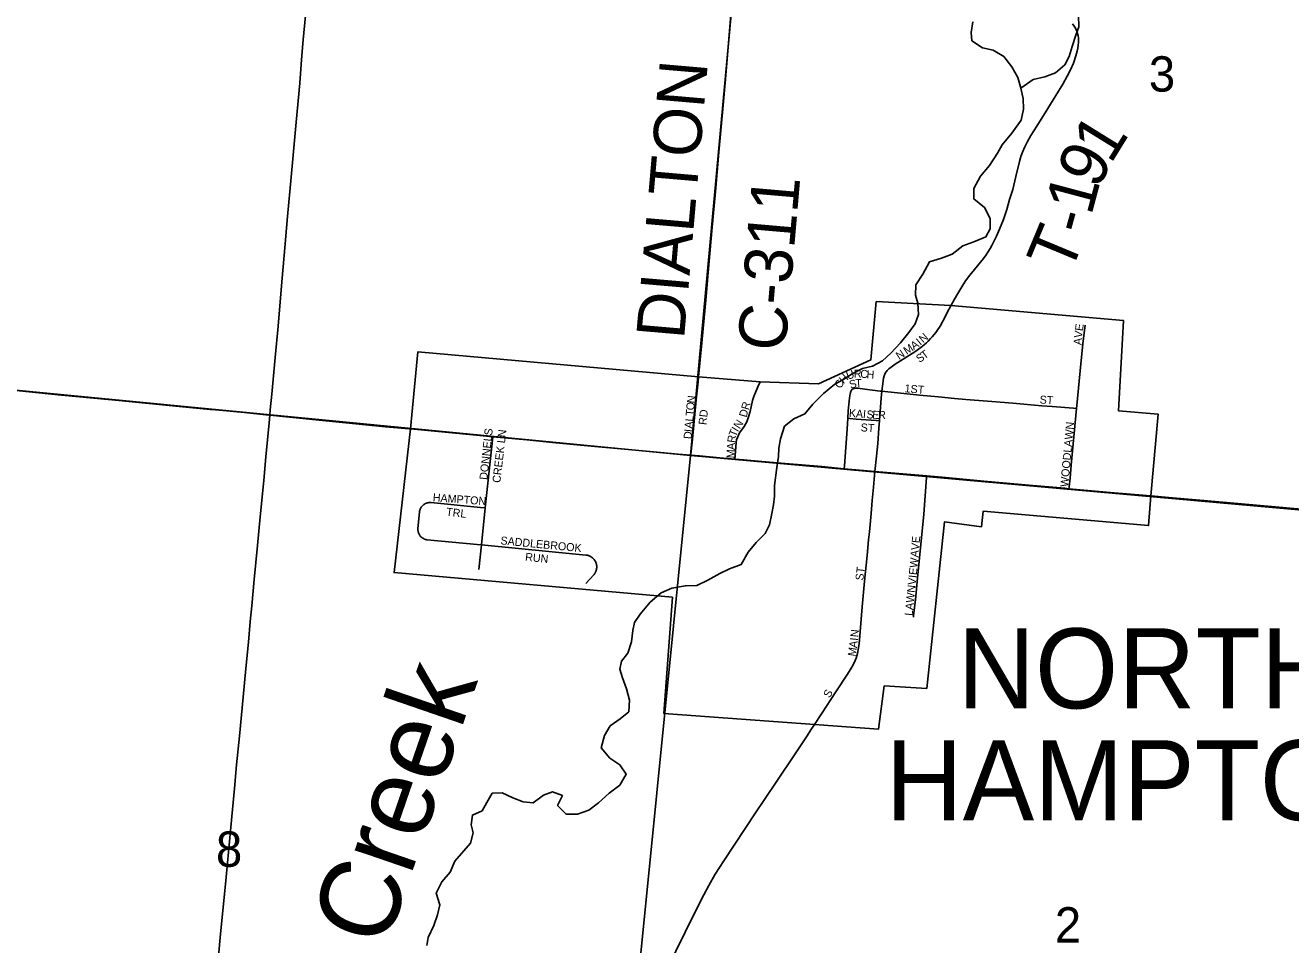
# Model space of a CAD drawing. Extents: x 1410790 to 1770854, y 566777 to 831614.
# Drawn here: x 1559702 to 1567610, y 725192 to 730938 of the extents above; entities that cross this region are included whole.
import ezdxf

# ---------------------------------------------------------------- set-up
doc = ezdxf.new("R2010")
doc.units = 0
for name, color, linetype in [('GM_X_City_Street', 7, 'Continuous'), ('GM_X_City_Street_Text', 7, 'Continuous'), ('GM_X_Corporation', 7, 'Continuous'), ('GM_X_Corporation_Text', 7, 'Continuous'), ('GM_X_County_Road', 7, 'Continuous'), ('GM_X_County_Road_Text', 7, 'Continuous'), ('GM_X_Minor_River', 7, 'Continuous'), ('GM_X_Minor_River_Text', 7, 'Continuous'), ('GM_X_Section', 7, 'Continuous'), ('GM_X_Section_Text', 7, 'Continuous'), ('GM_X_State_Route', 7, 'Continuous'), ('GM_X_Township_Road', 7, 'Continuous'), ('GM_X_Township_Road_Text', 7, 'Continuous')]:
    doc.layers.add(name, color=color, linetype=linetype)

msp = doc.modelspace()

# ---------------------------------------------------------------- linework, layer by layer
at = {"layer": 'GM_X_City_Street'}
for points in [[(1565055.7, 728650.6), (1565058.9, 728682.2), (1565060.2, 728698.3), (1565063.4, 728719.1), (1565065.8, 728733.3), (1565069.6, 728747.9), (1565072.8, 728756.9), (1565076.2, 728764.2), (1565081.1, 728772.2), (1565087.4, 728779.8), (1565098.4, 728790.9), (1565112.5, 728800.8), (1565139, 728820.8), (1565260.2, 728897.8), (1565299.5, 728924.6), (1565319.3, 728940.2), (1565333.5, 728953.4), (1565345.3, 728964.5), (1565359.9, 728980.1), (1565369.9, 728991), (1565382.1, 729005.5), (1565391.6, 729017.2), (1565401.2, 729030.5), (1565418.5, 729057.5), (1565449.9, 729115.6), (1565463.9, 729143.2), (1565485.7, 729185.7)], [(1566271.3, 728543.2), (1566273, 728560.9), (1566298, 728821.3), (1566313.3, 728966.5), (1566325.2, 729063.4)], [(1563860.9, 728251.6), (1563861.5, 728256.9), (1563872, 728350.6), (1563895.2, 728596.8), (1563907, 728709.7), (1563909.2, 728740.9)], [(1564136.6, 728226.6), (1564138.3, 728248.8), (1564144.8, 728330.5), (1564147.6, 728346.6), (1564152.1, 728362.3), (1564158.2, 728377.4), (1564166.4, 728391.6), (1564194.9, 728431.3), (1564203.2, 728445.4), (1564210.7, 728459.9), (1564222.2, 728491.8), (1564231.4, 728524), (1564247.3, 728593), (1564255.1, 728618.1), (1564279.8, 728678.5), (1564295, 728709.3)], [(1564841.5, 728482.3), (1564843.6, 728526.4), (1564849.8, 728591.8), (1564854.8, 728623.8), (1564856.3, 728633.4), (1564858.9, 728643.9), (1564861, 728649.6), (1564865.4, 728658.7)], [(1564865.4, 728658.7), (1564869.6, 728663.1), (1564875.1, 728666), (1564884.2, 728668.6), (1564892.3, 728669.4), (1564900.1, 728669.9), (1564910, 728669.4), (1564920.4, 728668.3), (1564948.4, 728664.5), (1565044.6, 728652.2), (1565055.7, 728650.6)], [(1565039.8, 728466.8), (1565040.1, 728471.1), (1565046, 728551.5), (1565051.2, 728608.1), (1565055.7, 728650.6)], [(1565055.7, 728650.6), (1565073.4, 728648.5), (1565290, 728625.8), (1565408.4, 728615.2), (1565508.2, 728606.3), (1565579.7, 728600.1), (1565741.9, 728586.9), (1565873.4, 728575.6), (1566054.3, 728560.1), (1566120.1, 728554.9), (1566253.6, 728544.6), (1566271.3, 728543.2)], [(1566224.3, 728041.7), (1566225.4, 728052.9), (1566231.3, 728108.5), (1566238.2, 728188.2), (1566254.6, 728366.5), (1566271.3, 728543.2)], [(1564819.6, 728166.6), (1564820.7, 728183.9), (1564830.6, 728299.5), (1564838.2, 728413.2), (1564841.5, 728482.3)], [(1564841.5, 728482.3), (1564855.2, 728481.1), (1564894.9, 728477.5), (1564957.3, 728473.1), (1565018.9, 728468.4), (1565039.8, 728466.8)], [(1565011.6, 728148.9), (1565021.4, 728245.1), (1565029, 728325.3), (1565036.3, 728420.4), (1565039.8, 728466.8)], [(1562576.7, 727922.5), (1562623, 728366.1), (1562623.1, 728366.7)], [(1564633.3, 726569.2), (1564677, 726635.4), (1564767.9, 726772.6), (1564840.3, 726882.3), (1564874.6, 726937.6), (1564888.8, 726967.4), (1564893.9, 726981.9), (1564902, 727012.3), (1564912.3, 727073), (1564932.3, 727303.4), (1564946.2, 727463.6), (1564962.7, 727623.9), (1564972.1, 727722.9), (1564977.3, 727772.5), (1564987.7, 727887.4), (1564995, 727968.3), (1565003, 728051.3), (1565007.5, 728101.3), (1565011.6, 728148.9)], [(1565252.9, 727238.9), (1565253.8, 727249.5), (1565264.9, 727347), (1565275.1, 727462.1), (1565290.8, 727610.6), (1565316.5, 727882.2), (1565334.4, 728112), (1565335.2, 728121.5)], [(1562576.7, 727922.5), (1562546.6, 727925.4), (1562235.8, 727955), (1562232.6, 727955.1), (1562229.4, 727955.2), (1562226.2, 727955), (1562223.1, 727954.7), (1562219.9, 727954.3), (1562216.8, 727953.7), (1562213.7, 727952.9), (1562210.7, 727952.1), (1562207.7, 727951), (1562204.7, 727949.8), (1562201.9, 727948.5), (1562199, 727947), (1562196.3, 727945.4), (1562193.6, 727943.7), (1562191.1, 727941.8), (1562188.6, 727939.8), (1562186.2, 727937.8), (1562183.9, 727935.5), (1562181.8, 727933.2), (1562179.7, 727930.8), (1562177.8, 727928.2), (1562176, 727925.6), (1562174.3, 727922.9), (1562172.8, 727920.2), (1562171.4, 727917.3), (1562170.1, 727914.4), (1562169, 727911.4), (1562168, 727908.4), (1562167.2, 727905.3), (1562166.6, 727902.3), (1562166, 727899.1), (1562165.7, 727896), (1562156.2, 727794), (1562155.9, 727790.9), (1562155.8, 727787.7), (1562155.9, 727784.5), (1562156.1, 727781.3), (1562156.5, 727778.1), (1562157, 727775), (1562157.6, 727771.9), (1562158.5, 727768.8), (1562159.5, 727765.8), (1562160.6, 727762.8), (1562161.9, 727759.9), (1562163.3, 727757), (1562164.9, 727754.3), (1562166.5, 727751.5), (1562168.4, 727748.9), (1562170.3, 727746.4), (1562172.4, 727744), (1562174.6, 727741.7), (1562176.9, 727739.5), (1562179.3, 727737.4), (1562181.8, 727735.4), (1562184.4, 727733.6), (1562187.1, 727731.8), (1562189.9, 727730.3), (1562192.7, 727728.8), (1562195.6, 727727.5), (1562198.6, 727726.4), (1562201.6, 727725.3), (1562204.7, 727724.5), (1562207.8, 727723.8), (1562210.9, 727723.2), (1562214.1, 727722.9), (1562525.2, 727693.4), (1562552.6, 727690.8)], [(1562552.6, 727690.8), (1562576.7, 727922.5)], [(1562536.5, 727536.5), (1562552.6, 727690.8)], [(1562552.6, 727690.8), (1563205.2, 727627.1), (1563208.6, 727626.7), (1563212, 727626.2), (1563215.3, 727625.5), (1563218.7, 727624.7), (1563222, 727623.7), (1563225.2, 727622.6), (1563228.4, 727621.3), (1563231.5, 727619.9), (1563234.6, 727618.3), (1563237.6, 727616.6), (1563240.4, 727614.8), (1563243.2, 727612.8), (1563246, 727610.7), (1563248.6, 727608.5), (1563251.1, 727606.1), (1563253.5, 727603.6), (1563255.7, 727601.1), (1563257.9, 727598.4), (1563259.9, 727595.7), (1563261.8, 727592.8), (1563263.6, 727589.9), (1563265.2, 727586.8), (1563266.7, 727583.7), (1563268.1, 727580.6), (1563269.2, 727577.4), (1563270.3, 727574.1), (1563271.2, 727570.8), (1563271.9, 727567.4), (1563272.5, 727564.1), (1563273, 727560.7), (1563273.2, 727557.2), (1563273.3, 727553.8), (1563273.3, 727550.3), (1563273.1, 727546.9), (1563272.7, 727543.5), (1563272.2, 727540.1), (1563271.5, 727536.8), (1563270.7, 727533.5), (1563269.7, 727530.1), (1563268.6, 727526.9), (1563267.3, 727523.7), (1563265.9, 727520.6), (1563264.3, 727517.5), (1563262.6, 727514.6), (1563260.8, 727511.7), (1563258.8, 727508.9), (1563256.7, 727506.2), (1563254.5, 727503.6), (1563205.5, 727448.5)]]:
    msp.add_lwpolyline(points, dxfattribs=at)
at = {"layer": 'GM_X_Corporation'}
msp.add_lwpolyline([(1563693.3, 726638), (1563746.3, 727363.8), (1562007.2, 727517.7), (1562109.2, 728415.5), (1562154.8, 728896.4), (1563909.2, 728740.9), (1564295, 728709.3), (1564659.7, 728696.6), (1564986.1, 728846.8), (1565020.1, 729211.8), (1565485.7, 729185.8), (1566564.4, 729093.2), (1566533.8, 728529.1), (1566781, 728508.1), (1566735.2, 727997.1), (1566722.1, 727811.8), (1565689, 727902.5), (1565677.2, 727804.6), (1565445.9, 727834.2), (1565335.7, 726793.5), (1565070.1, 726809.1), (1565034.7, 726540.1)], close=True, dxfattribs=at)
at = {"layer": 'GM_X_County_Road'}
for points in [[(1563909.2, 728740.9), (1563929.7, 728952.6), (1563956.3, 729242.8), (1563970, 729393.1), (1563993.5, 729654.4), (1564015.7, 729899.3), (1564036.7, 730144.3), (1564063.1, 730438.4), (1564078.1, 730601.6), (1564104.5, 730928.4), (1564122.4, 731140.8), (1564140, 731353.3), (1564176, 731761.6), (1564194.1, 731974.1), (1564208.8, 732137.3), (1564228.6, 732349.6), (1564247.7, 732561.9), (1564259.3, 732686)], [(1564587.6, 726498.1), (1564612.2, 726535.6), (1564633.3, 726569.2)], [(1563376.8, 724146.6), (1563381.6, 724160.4), (1563481.2, 724438.2), (1563571.2, 724684.6), (1563629.1, 724838), (1563672.2, 724944.2), (1563711.5, 725034.2), (1563768, 725152.5), (1563826.4, 725269.9), (1563927.4, 725476), (1563973.3, 725562.9), (1564014.1, 725633.8), (1564066.5, 725716.9), (1564266.2, 726017.2), (1564394, 726207.9), (1564513.1, 726384.8), (1564587.6, 726498.1)]]:
    msp.add_lwpolyline(points, dxfattribs=at)
at = {"layer": 'GM_X_Minor_River'}
for points in [[(1565922.9, 730545.4), (1566000, 730599.6), (1566074.4, 730616.7), (1566140.9, 730639.9), (1566197.7, 730691.3), (1566226.4, 730743.1), (1566245.2, 730805), (1566268.2, 730876.9), (1566286.8, 730928.8), (1566283.7, 730999), (1566274.6, 731075.3), (1566277.6, 731153.4), (1566294.4, 731219.4), (1566297.3, 731293.5), (1566276.2, 731365.9), (1566260.8, 731426.2), (1566287.8, 731494.1), (1566300.6, 731564.1), (1566291, 731657.4)], [(1565732.7, 729730.9), (1565697.4, 729799.5), (1565629.9, 729852.5), (1565630.7, 729918.7), (1565671.7, 729994.3), (1565728.7, 730061.8), (1565777.8, 730139.3), (1565806.5, 730191.1), (1565867.6, 730264.5), (1565924.7, 730346), (1565939.6, 730413.9), (1565938.4, 730480.1), (1565921.2, 730552.5), (1565903.9, 730610.8), (1565866.6, 730677.4), (1565817.3, 730742.2), (1565751.6, 730783.1), (1565683.6, 730798), (1565617.9, 730840.9), (1565612.6, 730893.1), (1565623.4, 730959.2)], [(1562211.5, 725187.7), (1562220.1, 725237.7), (1562255.1, 725311.5), (1562278, 725379.3), (1562292.8, 725441.3), (1562269.6, 725513.8), (1562304.6, 725585.5), (1562357.5, 725645), (1562386.4, 725714.8), (1562484, 725825.9), (1562500.9, 725891.9), (1562489.5, 725942.1), (1562496.2, 726002.2), (1562556.7, 726029.5), (1562587.4, 726081.3), (1562620.2, 726139), (1562682.4, 726140.2), (1562748.2, 726109.4), (1562814.1, 726084.5), (1562876.2, 726077.7), (1562941, 726127.1), (1562997.4, 726148.4), (1563059.3, 726123.6), (1563028.4, 726061.8), (1563081.9, 726007.1), (1563152.1, 726008.2), (1563224.6, 726033.4), (1563283.3, 726078.8), (1563350.3, 726140.1), (1563417, 726189.4), (1563458, 726257), (1563416.6, 726315.7), (1563354.9, 726358.5), (1563301.6, 726421.4), (1563322.6, 726499.3), (1563357.4, 726559), (1563420.1, 726604.3), (1563474.8, 726647.8), (1563477.7, 726719.9), (1563458.5, 726790.3), (1563433.3, 726860.8), (1563417.9, 726913.1), (1563428.5, 726963.1), (1563467.3, 727014.7), (1563490.2, 727084.6), (1563499.1, 727154.7), (1563509.7, 727204.7), (1563544.5, 727258.4), (1563607.6, 727331.8), (1563676.5, 727391), (1563743, 727420.3), (1563827.4, 727435.3), (1563899.6, 727436.4), (1563968.2, 727469.6), (1564043, 727512.8), (1564103.5, 727540.1), (1564176, 727567.3), (1564219, 727644.9), (1564269.9, 727706.5), (1564324.8, 727761.9), (1564353.5, 727815.7), (1564368.4, 727887.7), (1564377.1, 727941.7), (1564383.8, 727995.7), (1564384.6, 728061.9), (1564398, 728174), (1564408.9, 728244), (1564411.5, 728296.1), (1564422.3, 728354.1), (1564447.3, 728432), (1564506, 728479.3), (1564574.6, 728510.6), (1564623.5, 728570.1), (1564690.5, 728637.4), (1564761.4, 728694.7), (1564811.8, 728722.1), (1564870.5, 728759.5), (1564935, 728792.7), (1564997.4, 728808), (1565060, 728841.3), (1565110.7, 728888.8), (1565171.7, 728954.2), (1565224.6, 729017.6), (1565263.3, 729071.3), (1565284.1, 729131.2), (1565279, 729201.4), (1565265.6, 729251.7), (1565268.3, 729315.8), (1565311.3, 729383.4), (1565352.3, 729459.1), (1565426.8, 729482.2), (1565495.3, 729507.4), (1565560.1, 729560.7), (1565630.6, 729583.9), (1565705.2, 729615), (1565731.9, 729666.8), (1565732.7, 729730.9)]]:
    msp.add_lwpolyline(points, dxfattribs=at)
at = {"layer": 'GM_X_Section'}
for points in [[(1559098.4, 734120.8), (1564357.6, 733651.2), (1563860.1, 728250.4), (1558607.5, 728757.4)], [(1569584.1, 733136.2), (1569081.4, 727783.8), (1563860.1, 728250.4), (1564357.6, 733651.2)], [(1558607.5, 728757.4), (1563860.1, 728250.4), (1563332.6, 722968), (1558107.7, 723456.7)], [(1563860.1, 728250.4), (1569081.4, 727783.8), (1568614.4, 722540.4), (1563332.6, 722968)]]:
    msp.add_lwpolyline(points, close=True, dxfattribs=at)
at = {"layer": 'GM_X_State_Route'}
for points in [[(1560856.7, 728537.9), (1560663, 728556.3), (1560287.5, 728592.7), (1559928.4, 728627.3), (1559585.7, 728661.8)], [(1561224.7, 728502.4), (1561071.1, 728517.4), (1560891.5, 728534.6), (1560856.7, 728537.9)], [(1562104.5, 728416), (1562102, 728416.2), (1561952.2, 728429.1), (1561642.2, 728460.5), (1561332.2, 728491.9), (1561229.9, 728501.9), (1561224.7, 728502.4)], [(1566734.2, 727997.2), (1566685.9, 728001.6), (1566506.7, 728016.2), (1566224.3, 728041.7), (1566197.7, 728044.3), (1565998, 728062.7), (1565692.8, 728089.1), (1565431.4, 728113.4), (1565335.2, 728121.5), (1565011.6, 728148.9), (1564939.4, 728155.4), (1564819.6, 728166.6), (1564679.6, 728179.7), (1564451.5, 728199.9), (1564306, 728212), (1564190.7, 728221.8), (1564136.6, 728226.6), (1564042.5, 728235), (1563915.4, 728246.8), (1563860.9, 728251.6), (1563783.1, 728258.6), (1563651.9, 728270.4), (1563423.7, 728290.9), (1563261.6, 728305.8), (1563017.5, 728328.4), (1562836.9, 728347.5), (1562695.6, 728360.3), (1562623.1, 728366.7), (1562542.8, 728373.8), (1562109.2, 728415.5), (1562104.5, 728416)], [(1567770.5, 727905.1), (1567231.4, 727952.8), (1567019.1, 727971.7), (1566872, 727984.4), (1566735.2, 727997.1), (1566734.2, 727997.2)]]:
    msp.add_lwpolyline(points, dxfattribs=at)
at = {"layer": 'GM_X_Township_Road'}
for points in [[(1561229.9, 728501.9), (1561232.7, 728534.9), (1561242.1, 728632.7), (1561264.5, 728861.2), (1561282.4, 729057.2), (1561306.2, 729335), (1561319.4, 729498.5), (1561341.8, 729743.5), (1561363.6, 729988.6), (1561394.6, 730331.6), (1561417.2, 730576.6), (1561427.8, 730723.7), (1561439.3, 730846.4), (1561453.5, 730999.3)], [(1565485.7, 729185.7), (1565508.3, 729226.6), (1565529, 729262.1), (1565566.7, 729323.9), (1565577.7, 729340.9), (1565604.4, 729377.3), (1565633.1, 729411.8), (1565689.4, 729479.7), (1565706.6, 729503.5), (1565717.8, 729519.7), (1565732.5, 729543.4), (1565741.8, 729561.1), (1565770.7, 729619.5), (1565790.6, 729664.1), (1565814.7, 729724.5), (1565835.4, 729786.3), (1565853.7, 729849), (1565872.6, 729911.2), (1565892.1, 729993.2), (1565914.9, 730086.3), (1565924.1, 730117.6), (1565934.5, 730145.6), (1565948.3, 730179.3), (1565963.1, 730208.1), (1565986.9, 730249.5), (1566023, 730307.7), (1566091.4, 730417), (1566141.4, 730498.7), (1566185.1, 730570), (1566214, 730620.7), (1566233.6, 730658.8), (1566252.5, 730701.9), (1566268.2, 730746.9), (1566275.9, 730776.6), (1566279.5, 730795.1), (1566281.5, 730812.8), (1566283.1, 730830.5), (1566283.9, 730845.8), (1566283.1, 730860.3), (1566281.9, 730872.3), (1566278.7, 730886.8), (1566274.7, 730898.4), (1566269.8, 730908.9), (1566264.2, 730919.8), (1566256.2, 730933), (1566246.1, 730947.9)], [(1560900.9, 725025.7), (1560920.3, 725238), (1560956.9, 725613.3), (1560979.5, 725860), (1560997.4, 726037.8), (1561009.9, 726168.3), (1561022.2, 726315.4), (1561040.1, 726494.7), (1561063.9, 726739.5), (1561080.3, 726919.1), (1561097.2, 727082.1), (1561108.3, 727212.8), (1561118.1, 727310.7), (1561132.9, 727473.8), (1561153.4, 727686), (1561170.2, 727865.7), (1561192.6, 728094.2), (1561206, 728241.2), (1561225.9, 728453.3), (1561229.9, 728501.9)]]:
    msp.add_lwpolyline(points, dxfattribs=at)

# ---------------------------------------------------------------- texts
at = {"layer": 'GM_X_City_Street_Text'}
for s, rotation, p in [('N', 40.98626, (1565313.2, 728949.9)), ('V', 82.79095, (1566305.3, 728981.4)), ('E', 82.24467, (1566310.8, 729024.9)), ('M', 33.75858, (1565210.6, 728877.5)), ('A', 34.4736, (1565255, 728907.2)), ('I', 39.40889, (1565295.1, 728935)), ('A', 86.61043, (1566302.8, 728938.3)), ('N', 33.73856, (1565163, 728845.7)), ('S', 33.81891, (1565289.9, 728827)), ('T', 36.53146, (1565321.3, 728848.1)), ('U', 18.78051, (1564842.5, 728722.3)), ('R', 0.24288, (1564879.9, 728735.8)), ('C', 355.9888, (1564918.6, 728736)), ('H', 355.42695, (1564957.9, 728733.2)), ('C', 58.02808, (1564797, 728663.5)), ('H', 44.2736, (1564815.9, 728694.6)), ('S', 17.19916, (1564860.1, 728666)), ('T', 2.76009, (1564890.5, 728675.8)), ('1ST', 355.03354, (1565195.4, 728644.9)), ('N', 83.14333, (1563885.5, 728573.4)), ('ST', 356.42537, (1566040, 728574.5)), ('T', 84.80309, (1563878.3, 728494.9)), ('O', 84.81239, (1563881.5, 728530)), ('RD', 83.9832, (1563958.7, 728438.4)), ('DR', 74.06151, (1564209, 728484.3)), ('K', 355.64655, (1564847.7, 728490.9)), ('A', 355.62476, (1564891.6, 728487.5)), ('I', 355.63369, (1564935.5, 728484.2)), ('S', 355.62435, (1564957.4, 728482.5)), ('A', 84.80048, (1563871.2, 728416)), ('L', 84.80675, (1563875.2, 728459.8)), ('N', 56.54636, (1564166.1, 728411.5)), ('E', 357.2005, (1564994, 728479.7)), ('R', 359.62584, (1565031.5, 728478)), ('WOODLAWN', 84.68679, (1566219.2, 728050.8)), ('DONNELS', 83.85362, (1562589.3, 728095.3)), ('CREEK LN', 83.29071, (1562670.3, 728076.5)), ('D', 84.81348, (1563865.2, 728350.3)), ('I', 84.80647, (1563869.2, 728394.1)), ('R', 81.93514, (1564137.7, 728326.4)), ('T', 67.66592, (1564142.4, 728362.4)), ('I', 58.3839, (1564154.8, 728393.1)), ('ST', 356.42622, (1564921.4, 728400.6)), ('A', 87.59494, (1564136, 728283.7)), ('M', 87.61329, (1564133.8, 728231)), ('HAMPTON', 355.85451, (1562247.3, 727962.9)), ('TRL', 353.41359, (1562330.3, 727873.9)), ('SADDLEBROOK', 354.45544, (1562669.9, 727694.5)), ('AVE', 84.28507, (1565282, 727611.2)), ('RUN', 354.08949, (1562824, 727592.2)), ('LAWNVIEW', 84.14426, (1565246.8, 727245.7)), ('ST', 83.29314, (1564938.8, 727466.2)), ('I', 84.0062, (1564905, 727089.9)), ('N', 84.27026, (1564907.4, 727112)), ('M', 81.09459, (1564890.5, 726991.4)), ('A', 82.14608, (1564898.8, 727044.5)), ('S', 60.24503, (1564728.8, 726730.6))]:
    msp.add_text(s, height=50, rotation=rotation, dxfattribs=at).set_placement(p)
at = {"layer": 'GM_X_Corporation_Text'}
for s, p in [('NORTH', (1565529, 726669)), ('HAMPTON', (1565078, 725970.2))]:
    msp.add_text(s, height=500, rotation=0.00001, dxfattribs=at).set_placement(p)
at = {"layer": 'GM_X_County_Road_Text'}
for s, rotation, p in [('DIALTON', 85.06985, (1563818.6, 728971.1)), ('C-311', 85.05377, (1564451.1, 728894.4))]:
    msp.add_text(s, height=300, rotation=rotation, dxfattribs=at).set_placement(p)
at = {"layer": 'GM_X_Minor_River_Text'}
msp.add_text('Creek', height=499.84, rotation=71.00242, dxfattribs=at).set_placement((1561951.6, 725157.8))
at = {"layer": 'GM_X_Section_Text'}
for s, p in [('3', (1566723.6, 730523.4)), ('8', (1560893.6, 725679)), ('2', (1566136.2, 725205.5))]:
    msp.add_text(s, height=221, rotation=0.00001, dxfattribs=at).set_placement(p)
at = {"layer": 'GM_X_Township_Road_Text'}
for s, rotation, p in [('1', 58.26601, (1566484.6, 730065.4)), ('9', 63.36978, (1566405.2, 729906.4)), ('1', 75.08675, (1566363.4, 729743)), ('-', 74.46149, (1566329.5, 729620.8)), ('T', 67.42661, (1566230.2, 729375.7))]:
    msp.add_text(s, height=300, rotation=rotation, dxfattribs=at).set_placement(p)

doc.saveas('drawing.dxf')
